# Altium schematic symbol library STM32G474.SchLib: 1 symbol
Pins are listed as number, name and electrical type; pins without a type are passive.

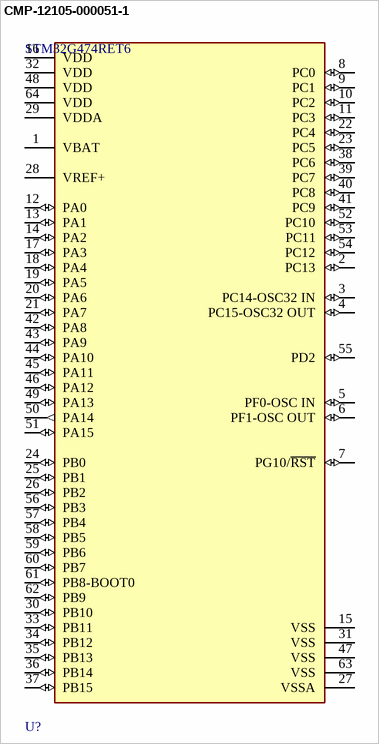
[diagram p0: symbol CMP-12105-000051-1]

## CMP-12105-000051-1
designator U?, comment STM32G474RET6
MAINSTREAM ARM CORTEX-M4 CORE WI; Manufacturer: STMicroelectronics; Ram Size: 128KBytes; Interface: I2C,SPI,UART,USART,CAN,USB,LIN,IrDA,I2S,SMBus,Other; Number Of I2C Channels: 4; Number Of A/D Converters: 5; Number Of Timers/Counters: 14; Number Of I/Os: 52; Max Supply Voltage: 3.6V; Memory Size: 512KBytes; Number Of Adc Channels: 26; Number Of Cores: 1; Min Supply Voltage: 1.71V; Max Junction Temp: +105°C; Standoff Height: 0.05mm; Number Of Uart Channels: 6; Number Of Spi Channels: 3; Frequency: 170MHz; Data Bus Width: 32bits; Memory Type: FLASH; Number Of Pwm Channels: 32
footprint FP-LQFP64-5W-IPC_B
footprint FP-LQFP64-5W-MFG
footprint FP-LQFP64-5W-IPC_C
footprint FP-LQFP64-5W-IPC_A
pins: 1 VBAT (power), 2 PC13 (io), 3 PC14-OSC32 IN (io), 4 PC15-OSC32 OUT (io), 5 PF0-OSC IN (io), 6 PF1-OSC OUT (io), 7 PG10/~{RST} (io), 8 PC0 (io), 9 PC1 (io), 10 PC2 (io), 11 PC3 (io), 12 PA0 (io), 13 PA1 (io), 14 PA2 (io), 15 VSS (power), 16 VDD (power), 17 PA3 (io), 18 PA4 (io), 19 PA5 (io), 20 PA6 (io), 21 PA7 (io), 22 PC4 (io), 23 PC5 (io), 24 PB0 (io), 25 PB1 (io), 26 PB2 (io), 27 VSSA (power), 28 VREF+ (power), 29 VDDA (power), 30 PB10 (io), 31 VSS (power), 32 VDD (power), 33 PB11 (io), 34 PB12 (io), 35 PB13 (io), 36 PB14 (io), 37 PB15 (io), 38 PC6 (io), 39 PC7 (io), 40 PC8 (io), 41 PC9 (io), 42 PA8 (io), 43 PA9 (io), 44 PA10 (io), 45 PA11 (io), 46 PA12 (io), 47 VSS (power), 48 VDD (power), 49 PA13 (io), 50 PA14 (out), 51 PA15 (io), 52 PC10 (io), 53 PC11 (io), 54 PC12 (io), 55 PD2 (io), 56 PB3 (io), 57 PB4 (io), 58 PB5 (io), 59 PB6 (io), 60 PB7 (io), 61 PB8-BOOT0 (io), 62 PB9 (io), 63 VSS (power), 64 VDD (power)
